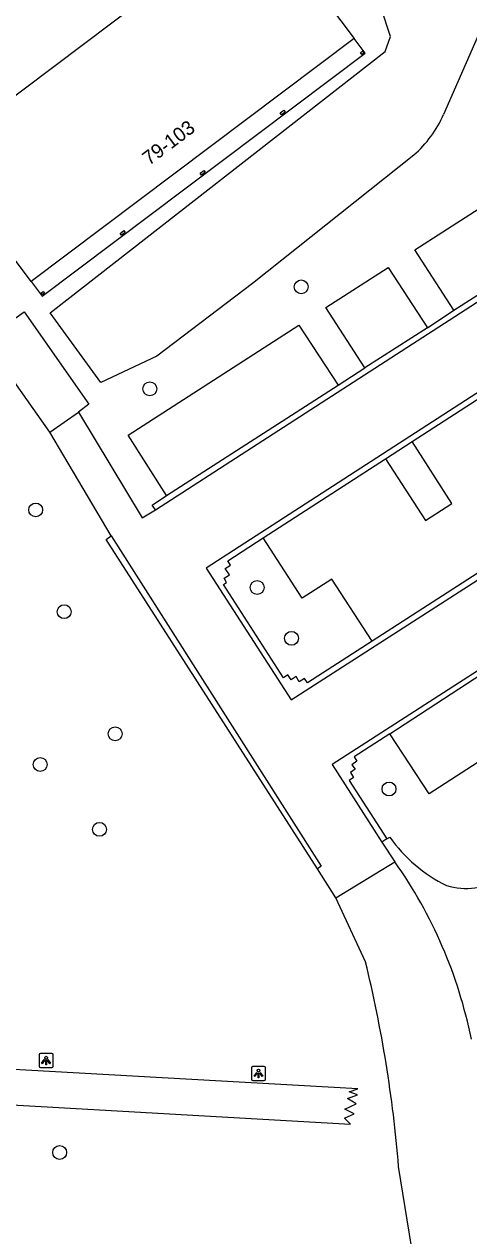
# Model space of a CAD drawing. Extents: x 159451 to 160663, y 388402 to 389723.
# Drawn here: x 159589.3 to 159620.6, y 389293.3 to 389378.7 of the extents above; entities that cross this region are included whole.
import ezdxf

# ---------------------------------------------------------------- set-up
doc = ezdxf.new("R2010")
doc.units = 0
for name, color, linetype in [('IMGEO_Boom', 7, 'Continuous'), ('IMGEO_Lichtpunt', 7, 'Continuous'), ('IMGEO_Meer_plas_ven_vijver', 7, 'Continuous'), ('IMGEO_Pand', 7, 'Continuous'), ('IMGEO_Pand_nummerreeks', 7, 'Continuous'), ('IMGEO_Pand_overbouw', 7, 'Continuous'), ('IMGEO_Parkeervlak_halfverhard', 7, 'Continuous'), ('IMGEO_Rijbaan_lokaal_gesloten', 7, 'Continuous'), ('IMGEO_Rijbaan_lokaal_halfverhard', 7, 'Continuous'), ('IMGEO_Rijbaan_lokaal_open', 7, 'Continuous'), ('IMGEO_Voetpad_halfverhard', 7, 'Continuous')]:
    doc.layers.add(name, color=color, linetype=linetype)

msp = doc.modelspace()

# ---------------------------------------------------------------- linework, layer by layer
at = {"layer": 'IMGEO_Boom'}
for centre in [(159608.795, 389360.145), (159598.128, 389352.957), (159590.081, 389344.426), (159605.686, 389338.963), (159592.081, 389337.252), (159608.103, 389335.378), (159595.675, 389328.648), (159590.4, 389326.482), (159614.981, 389324.755), (159594.58, 389321.911), (159591.767, 389299.135)]:
    msp.add_circle(centre, 0.489, dxfattribs=at)
at = {"layer": 'IMGEO_Lichtpunt'}
for p, q in [((159590.313, 389306.022), (159590.313, 389305.215)), ((159590.313, 389306.022), (159590.313, 389305.215)), ((159591.215, 389306.117), (159590.407, 389306.117)), ((159591.215, 389306.117), (159590.407, 389306.117)), ((159591.309, 389305.215), (159591.309, 389306.022)), ((159591.309, 389305.215), (159591.309, 389306.022)), ((159590.407, 389305.121), (159591.215, 389305.121)), ((159590.407, 389305.121), (159591.215, 389305.121)), ((159605.279, 389305.114), (159605.279, 389304.307)), ((159605.279, 389305.114), (159605.279, 389304.307)), ((159606.181, 389305.209), (159605.373, 389305.209)), ((159606.181, 389305.209), (159605.373, 389305.209)), ((159606.275, 389304.307), (159606.275, 389305.114)), ((159606.275, 389304.307), (159606.275, 389305.114)), ((159605.373, 389304.213), (159606.181, 389304.213)), ((159605.373, 389304.213), (159606.181, 389304.213))]:
    msp.add_line(p, q, dxfattribs=at)
for points in [[(159590.687, 389305.686), (159590.726, 389305.658), (159590.538, 389305.396), (159590.5, 389305.423), (159590.687, 389305.686)], [(159590.789, 389305.638), (159590.836, 389305.638), (159590.836, 389305.316), (159590.789, 389305.316), (159590.789, 389305.638)], [(159590.899, 389305.658), (159590.937, 389305.685), (159591.124, 389305.423), (159591.085, 389305.395), (159590.899, 389305.658)], [(159605.653, 389304.778), (159605.692, 389304.75), (159605.504, 389304.488), (159605.466, 389304.515), (159605.653, 389304.778)], [(159605.865, 389304.75), (159605.903, 389304.777), (159606.09, 389304.515), (159606.051, 389304.487), (159605.865, 389304.75)], [(159605.755, 389304.73), (159605.802, 389304.73), (159605.802, 389304.408), (159605.755, 389304.408), (159605.755, 389304.73)]]:
    msp.add_lwpolyline(points, dxfattribs=at)
for centre in [(159590.812, 389305.82), (159605.778, 389304.912)]:
    msp.add_circle(centre, 0.0994, dxfattribs=at)
for centre, start, end in [((159590.407, 389306.022), 90, 180), ((159590.407, 389306.022), 90, 180), ((159591.215, 389306.022), 0, 90), ((159591.215, 389306.022), 0, 90), ((159590.407, 389305.215), 180, 270), ((159590.407, 389305.215), 180, 270), ((159591.215, 389305.215), 270, 0), ((159591.215, 389305.215), 270, 360), ((159605.373, 389305.114), 90, 180), ((159605.373, 389305.114), 90, 180), ((159606.181, 389305.114), 0, 90), ((159606.181, 389305.114), 0, 90), ((159605.373, 389304.307), 180, 270), ((159605.373, 389304.307), 180, 270), ((159606.181, 389304.307), 270, 0), ((159606.181, 389304.307), 270, 360)]:
    msp.add_arc(centre, 0.0946, start, end, dxfattribs=at)
at = {"layer": 'IMGEO_Meer_plas_ven_vijver'}
for points in [[(159591.093, 389358.32), (159614.718, 389376.735), (159615.079, 389377.795), (159614.436, 389379.787), (159613.104, 389383.71), (159606.954, 389392.211)], [(159622.613, 389380.94), (159618.83, 389372.291)], [(159616.729, 389369.443), (159605.352, 389360.378), (159598.626, 389355.276), (159594.681, 389353.399), (159591.093, 389358.32)]]:
    msp.add_lwpolyline(points, dxfattribs=at)
msp.add_arc((159611.151, 389375.757), 8.425, 311.45918, 335.70764, dxfattribs=at)
at = {"layer": 'IMGEO_Pand'}
for points in [[(159589.76, 389360.534), (159583.054, 389369.444), (159605.812, 389386.575), (159612.526, 389377.663), (159589.76, 389360.534)], [(159613.074, 389376.537), (159612.978, 389376.665), (159613.122, 389376.773), (159613.218, 389376.645), (159613.074, 389376.537)], [(159607.668, 389372.469), (159607.412, 389372.277), (159607.316, 389372.405), (159607.571, 389372.597), (159607.668, 389372.469)], [(159602.028, 389368.226), (159601.772, 389368.033), (159601.676, 389368.161), (159601.931, 389368.354), (159602.028, 389368.226)], [(159596.392, 389363.985), (159596.138, 389363.795), (159596.04, 389363.921), (159596.295, 389364.113), (159596.392, 389363.985)], [(159590.563, 389359.6), (159590.467, 389359.728), (159590.595, 389359.824), (159590.691, 389359.696), (159590.563, 389359.6)]]:
    msp.add_lwpolyline(points, dxfattribs=at)
at = {"layer": 'IMGEO_Pand_overbouw'}
msp.add_lwpolyline([(159613.305, 389376.629), (159612.526, 389377.663), (159589.76, 389360.534), (159590.538, 389359.501)], close=True, dxfattribs=at)
at = {"layer": 'IMGEO_Parkeervlak_halfverhard'}
for points in [[(159619.55, 389358.499), (159616.804, 389362.759), (159623.307, 389366.937), (159626.095, 389362.677)], [(159613.267, 389354.447), (159610.538, 389358.687), (159614.923, 389361.525), (159617.692, 389357.266)], [(159599.303, 389345.442), (159596.586, 389349.686), (159608.624, 389357.451), (159611.385, 389353.224)], [(159613.795, 389335.171), (159610.949, 389339.542), (159608.859, 389338.202), (159606.105, 389342.451)], [(159621.512, 389332.869), (159624.252, 389328.571), (159617.799, 389324.41), (159615.031, 389328.65)]]:
    msp.add_lwpolyline(points, dxfattribs=at)
at = {"layer": 'IMGEO_Rijbaan_lokaal_gesloten'}
for points in [[(159598.522, 389344.436), (159626.787, 389362.691), (159629.682, 389358.16), (159602.087, 389340.314), (159608.085, 389331.051), (159635.706, 389348.811), (159638.659, 389344.315), (159610.982, 389326.488), (159614.479, 389321.018)], [(159591.074, 389349.897), (159586.47, 389356.404), (159589.258, 389358.394), (159593.822, 389351.872), (159593.097, 389351.323)], [(159591.074, 389349.897), (159593.097, 389351.323)], [(159593.097, 389351.323), (159597.59, 389343.867), (159598.522, 389344.436)], [(159595.399, 389342.61), (159591.074, 389349.897)], [(159595.399, 389342.61), (159610.199, 389319.324), (159609.928, 389319.12)], [(159614.816, 389321.244), (159614.479, 389321.018)], [(159614.479, 389321.018), (159615.389, 389319.623)], [(159614.816, 389321.244), (159615.036, 389321.364)], [(159611.239, 389317.075), (159615.389, 389319.623)], [(159611.239, 389317.075), (159609.928, 389319.12)], [(159613.321, 389312.584), (159611.239, 389317.075)], [(159568.631, 389303.617), (159612.27, 389301.143), (159611.84, 389301.566), (159612.513, 389301.851), (159611.86, 389302.198), (159612.655, 389302.565), (159612.044, 389302.952), (159612.757, 389303.197), (159612.166, 389303.421), (159612.776, 389303.614), (159569.711, 389306.038)], [(159618.859, 389278.354), (159615.655, 389298.149)]]:
    msp.add_lwpolyline(points, dxfattribs=at)
for centre, radius, start, end in [((159623.659, 389327.436), 10.547, 215.15277, 244.01351), ((159588.41, 389300.563), 33.033, 11.47784, 35.24014), ((159620.405, 389322.265), 4.521, 252.39623, 303.72326), ((159523.452, 389290.647), 92.508, 4.65164, 13.71772)]:
    msp.add_arc(centre, radius, start, end, dxfattribs=at)
at = {"layer": 'IMGEO_Rijbaan_lokaal_halfverhard'}
msp.add_lwpolyline([(159609.928, 389319.12), (159595.057, 389342.34), (159595.399, 389342.61)], dxfattribs=at)
at = {"layer": 'IMGEO_Rijbaan_lokaal_open'}
for points in [[(159619.55, 389358.499), (159626.095, 389362.677)], [(159617.692, 389357.266), (159619.55, 389358.499)], [(159617.692, 389357.266), (159613.267, 389354.447)], [(159616.602, 389349.25), (159629.417, 389357.527)], [(159611.385, 389353.224), (159613.267, 389354.447)], [(159599.303, 389345.442), (159611.385, 389353.224)], [(159614.728, 389348.033), (159616.602, 389349.25)], [(159606.105, 389342.451), (159614.728, 389348.033)], [(159632.897, 389347.493), (159613.795, 389335.171)], [(159598.522, 389344.436), (159598.283, 389344.767), (159599.303, 389345.442)], [(159613.795, 389335.171), (159609.225, 389332.233), (159609.021, 389332.541), (159608.644, 389332.299), (159608.431, 389332.683), (159608.09, 389332.442), (159607.85, 389332.804), (159607.536, 389332.597), (159603.313, 389339.166), (159603.525, 389339.305), (159603.362, 389339.61), (159603.744, 389339.863), (159603.444, 389340.289), (159603.806, 389340.526), (159603.628, 389340.828), (159606.105, 389342.451)], [(159615.031, 389328.65), (159621.512, 389332.869)], [(159615.031, 389328.65), (159612.521, 389327.021), (159612.713, 389326.719), (159612.36, 389326.469), (159612.602, 389326.158), (159612.271, 389325.917), (159612.466, 389325.57), (159612.173, 389325.361), (159614.816, 389321.244)]]:
    msp.add_lwpolyline(points, dxfattribs=at)
at = {"layer": 'IMGEO_Voetpad_halfverhard'}
msp.add_lwpolyline([(159614.728, 389348.033), (159617.552, 389343.678), (159619.409, 389344.88), (159616.602, 389349.25)], dxfattribs=at)

# ---------------------------------------------------------------- texts
at = {"layer": 'IMGEO_Pand_nummerreeks'}
msp.add_text('79-103', height=1, rotation=36.95578, dxfattribs=at).set_placement((159598.074, 389368.666))

doc.saveas('drawing.dxf')
